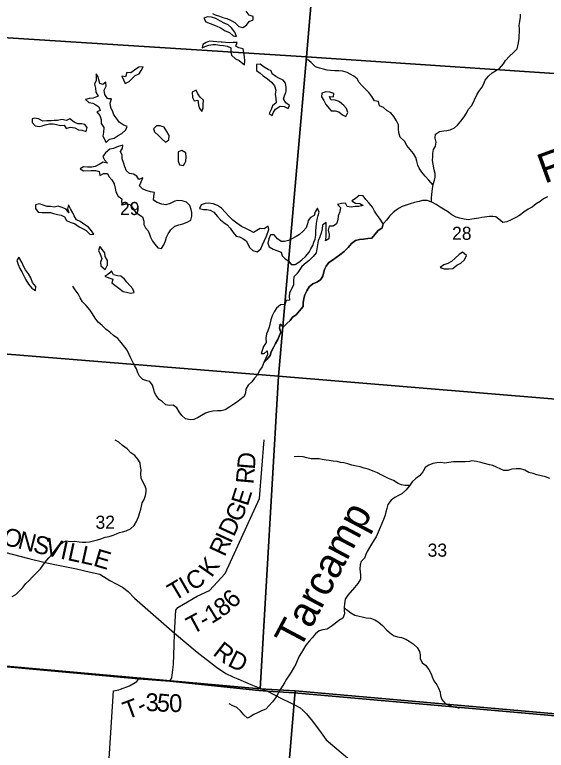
# Model space of a CAD drawing. Extents: x 1715311 to 2083412, y 146837 to 553079.
# Drawn here: x 1960786 to 1969763, y 377700 to 390110 of the extents above; entities that cross this region are included whole.
import ezdxf

# ---------------------------------------------------------------- set-up
doc = ezdxf.new("R2010")
doc.units = 0
for name, color, linetype in [('GM_X_County_Road', 7, 'Continuous'), ('GM_X_County_Road_Text', 7, 'Continuous'), ('GM_X_Minor_Lake', 7, 'Continuous'), ('GM_X_Minor_River', 7, 'Continuous'), ('GM_X_Minor_River_Text', 7, 'Continuous'), ('GM_X_Section', 7, 'Continuous'), ('GM_X_Section_Text', 7, 'Continuous'), ('GM_X_Township', 7, 'Continuous'), ('GM_X_Township_Road', 7, 'Continuous'), ('GM_X_Township_Road_Text', 7, 'Continuous'), ('GM_X_Township_ROW', 7, 'Continuous')]:
    doc.layers.add(name, color=color, linetype=linetype)

msp = doc.modelspace()

# ---------------------------------------------------------------- linework, layer by layer
at = {"layer": 'GM_X_County_Road'}
for points in [[(1960613, 381045), (1961027, 380934), (1961300, 380869), (1961548, 380819), (1961832, 380761), (1962066, 380704), (1962224, 380671), (1962390, 380567), (1962605, 380452), (1962702, 380380), (1962810, 380265), (1963484, 379677), (1963867, 379354), (1964196, 379103), (1964352, 378996), (1964470, 378940), (1964552, 378904)], [(1964552, 378904), (1964772, 378808), (1965054, 378699), (1965292, 378571), (1965431, 378505), (1965544, 378451), (1965604, 378417), (1965658, 378373), (1965716, 378315), (1965814, 378190), (1965960, 377994), (1966048, 377877), (1966550, 377450)]]:
    msp.add_lwpolyline(points, dxfattribs=at)
at = {"layer": 'GM_X_Minor_Lake'}
for points in [[(1964239, 389899), (1964271, 389881), (1964343, 389839), (1964411, 389811), (1964475, 389752), (1964529, 389744), (1964503, 389814), (1964449, 389887), (1964389, 389937), (1964325, 389967), (1964260, 390001), (1964184, 390046), (1964110, 390066), (1964044, 390074), (1963982, 390052)], [(1964127, 390130), (1964170, 390110), (1964246, 390084), (1964302, 390065), (1964366, 390047), (1964428, 390019), (1964501, 389979), (1964571, 389910), (1964641, 389892), (1964699, 389932), (1964747, 389998), (1964815, 390026), (1964811, 390080), (1964744, 390104), (1964696, 390172)], [(1963982, 390052), (1964012, 389990), (1964088, 389960), (1964158, 389934), (1964211, 389914), (1964239, 389899)], [(1964288, 389648), (1964274, 389649), (1964199, 389655), (1964137, 389660), (1964073, 389664), (1964017, 389644), (1963961, 389608), (1963950, 389554), (1964016, 389578), (1964066, 389598), (1964130, 389610), (1964182, 389607), (1964250, 389599), (1964312, 389593), (1964376, 389577), (1964438, 389550), (1964436, 389480), (1964446, 389430), (1964515, 389366), (1964579, 389340), (1964669, 389265)], [(1964669, 389265), (1964673, 389330), (1964667, 389402), (1964657, 389470), (1964642, 389534), (1964570, 389550), (1964518, 389580), (1964544, 389644), (1964476, 389644), (1964410, 389635), (1964344, 389641), (1964288, 389648)], [(1962945, 389211), (1962954, 389229), (1962880, 389226), (1962808, 389172), (1962750, 389128), (1962682, 389134), (1962658, 389064), (1962594, 389074)], [(1962594, 389074), (1962653, 388948), (1962721, 388982), (1962768, 389036), (1962820, 389082), (1962888, 389115), (1962924, 389167), (1962945, 389211)], [(1965363, 388799), (1965371, 388819), (1965371, 388885), (1965357, 388955), (1965319, 389007), (1965249, 389041), (1965198, 389070), (1965132, 389112), (1965116, 389162), (1965064, 389188), (1964998, 389224), (1964933, 389275), (1964867, 389271)], [(1964867, 389271), (1964870, 389167), (1964930, 389122), (1964982, 389080), (1965054, 389026), (1965123, 388972), (1965175, 388908), (1965195, 388839), (1965183, 388767), (1965196, 388695), (1965200, 388625), (1965138, 388571), (1965118, 388511), (1965084, 388446), (1965135, 388409), (1965158, 388465), (1965190, 388517), (1965268, 388565), (1965334, 388563), (1965404, 388528), (1965424, 388580), (1965366, 388623), (1965326, 388691), (1965340, 388743), (1965363, 388799)], [(1962370, 388693), (1962351, 388695), (1962309, 388763), (1962299, 388835), (1962332, 388905), (1962324, 388971), (1962274, 388931), (1962222, 388950), (1962206, 389012), (1962198, 389062), (1962164, 389114), (1962162, 389054), (1962162, 389002), (1962134, 388938), (1962148, 388870), (1962159, 388802), (1962193, 388735), (1962113, 388704), (1962043, 388698), (1961981, 388680), (1962037, 388630), (1962103, 388620), (1962155, 388589), (1962208, 388555), (1962232, 388493), (1962172, 388469), (1962226, 388409), (1962246, 388341), (1962245, 388273), (1962291, 388205), (1962287, 388129), (1962275, 388063), (1962328, 387952)], [(1963967, 388597), (1963977, 388669), (1963918, 388718), (1963880, 388774), (1963848, 388838), (1963784, 388802)], [(1962328, 387952), (1962388, 388008), (1962464, 388026), (1962536, 388070), (1962593, 388106), (1962665, 388167), (1962685, 388225), (1962615, 388250), (1962551, 388296), (1962515, 388346), (1962462, 388420), (1962442, 388472), (1962412, 388547), (1962397, 388617), (1962419, 388689), (1962370, 388693)], [(1963784, 388802), (1963788, 388714), (1963817, 388658), (1963877, 388668), (1963891, 388590), (1963903, 388540), (1963947, 388475), (1963969, 388539), (1963967, 388597)], [(1966248, 388649), (1966197, 388668), (1966127, 388674), (1966100, 388728), (1966168, 388724), (1966174, 388782), (1966106, 388802), (1966038, 388809), (1965972, 388785), (1965966, 388727), (1966008, 388663), (1966039, 388596), (1966129, 388486)], [(1966129, 388486), (1966197, 388486), (1966259, 388470), (1966324, 388423), (1966376, 388395), (1966412, 388459), (1966389, 388525), (1966343, 388577), (1966273, 388640), (1966248, 388649)], [(1962004, 388182), (1962009, 388206), (1961972, 388260), (1961914, 388268), (1961852, 388270), (1961788, 388297), (1961720, 388351), (1961660, 388325), (1961582, 388343), (1961508, 388323), (1961454, 388328), (1961400, 388320), (1961330, 388320), (1961262, 388316), (1961187, 388355), (1961121, 388367), (1961081, 388355)], [(1961081, 388355), (1961083, 388291), (1961134, 388235), (1961198, 388222), (1961250, 388236), (1961302, 388252), (1961376, 388268), (1961434, 388270), (1961494, 388255), (1961560, 388243), (1961624, 388245), (1961658, 388191), (1961724, 388215), (1961800, 388200), (1961863, 388168), (1961921, 388160), (1961993, 388140), (1962004, 388182)], [(1963368, 387982), (1963387, 387997), (1963396, 388075), (1963358, 388141), (1963310, 388213), (1963244, 388236), (1963179, 388236), (1963128, 388186)], [(1963128, 388186), (1963148, 388132), (1963212, 388074), (1963276, 388011), (1963335, 387957), (1963368, 387982)], [(1963079, 387121), (1963079, 387121), (1963009, 387142), (1962945, 387170), (1962895, 387224), (1962921, 387288), (1962950, 387356), (1962882, 387328), (1962848, 387384), (1962794, 387421), (1962726, 387429), (1962672, 387475), (1962647, 387545), (1962623, 387615), (1962603, 387679), (1962599, 387743), (1962572, 387800), (1962606, 387861), (1962614, 387911), (1962532, 387884), (1962456, 387854), (1962390, 387842), (1962318, 387780), (1962276, 387716), (1962303, 387662), (1962351, 387608), (1962279, 387622), (1962215, 387583), (1962145, 387547), (1962089, 387537), (1962017, 387537), (1961949, 387541), (1961893, 387512), (1961949, 387475), (1962077, 387479), (1962149, 387481), (1962215, 387463), (1962226, 387396), (1962286, 387430), (1962354, 387432), (1962374, 387382), (1962424, 387326), (1962466, 387256), (1962481, 387185), (1962495, 387121), (1962535, 387051), (1962593, 387005), (1962587, 386953), (1962606, 386903), (1962664, 386917), (1962728, 386906), (1962784, 386840), (1962828, 386776), (1962880, 386738), (1962943, 386700), (1962965, 386625), (1962967, 386573), (1962993, 386515), (1963040, 386461), (1963064, 386407), (1963082, 386357), (1963112, 386289)], [(1963545, 387798), (1963544, 387638), (1963570, 387576), (1963636, 387564), (1963663, 387616)], [(1963663, 387616), (1963674, 387638), (1963680, 387714), (1963678, 387782), (1963609, 387818), (1963545, 387798)], [(1963112, 386289), (1963152, 386237), (1963203, 386176), (1963265, 386168), (1963307, 386230), (1963332, 386294), (1963350, 386358), (1963376, 386414), (1963420, 386482), (1963490, 386544), (1963556, 386563), (1963628, 386581), (1963696, 386611), (1963758, 386643), (1963779, 386711), (1963777, 386775), (1963765, 386825), (1963743, 386891), (1963686, 386947), (1963614, 386968), (1963542, 386974), (1963488, 386966), (1963414, 386926), (1963340, 386904), (1963268, 386911), (1963194, 386941), (1963130, 386983), (1963136, 387047), (1963145, 387111), (1963079, 387121)], [(1967007, 386584), (1966944, 386678), (1966896, 386744), (1966864, 386796), (1966827, 386865), (1966771, 386929), (1966717, 386991), (1966671, 387053), (1966601, 387058), (1966537, 387004), (1966479, 386970), (1966543, 386928), (1966613, 386925), (1966669, 386891), (1966599, 386873), (1966535, 386876), (1966469, 386862), (1966401, 386874), (1966371, 386928), (1966305, 386926), (1966239, 386909), (1966289, 386856), (1966279, 386782), (1966249, 386717), (1966244, 386648), (1966222, 386583), (1966166, 386545), (1966094, 386545), (1966082, 386475), (1966096, 386401), (1966091, 386331), (1966035, 386295), (1966043, 386363), (1966046, 386431), (1966048, 386481), (1966048, 386543), (1966044, 386603), (1965986, 386561), (1965978, 386495), (1965962, 386427), (1965940, 386361), (1965909, 386293), (1965897, 386227), (1965889, 386161), (1965875, 386095), (1965827, 386028), (1965758, 385966), (1965706, 385922), (1965636, 385862), (1965590, 385796), (1965548, 385740), (1965498, 385686), (1965493, 385622), (1965493, 385546), (1965461, 385484), (1965429, 385414), (1965421, 385362), (1965424, 385292), (1965372, 385287), (1965348, 385219), (1965274, 385215), (1965208, 385159), (1965168, 385099), (1965132, 385031), (1965113, 384961), (1965097, 384891), (1965085, 384841), (1965059, 384779), (1965039, 384725), (1965026, 384655), (1965034, 384579), (1964988, 384511), (1964968, 384459), (1964946, 384393), (1965000, 384393), (1965050, 384439), (1965053, 384377), (1964995, 384243)], [(1961605, 386709), (1961625, 386700), (1961662, 386636), (1961732, 386604), (1961798, 386585), (1961872, 386533), (1961942, 386499), (1961993, 386467), (1962063, 386400), (1962125, 386406), (1962081, 386466), (1962030, 386525), (1961968, 386565), (1961894, 386621), (1961832, 386651), (1961790, 386715), (1961767, 386766), (1961729, 386836), (1961697, 386900), (1961679, 386836), (1961701, 386770), (1961655, 386832), (1961587, 386860), (1961523, 386878), (1961455, 386861), (1961389, 386877), (1961335, 386875), (1961266, 386899), (1961204, 386920), (1961136, 386904)], [(1961136, 386904), (1961137, 386840), (1961181, 386780), (1961249, 386773), (1961319, 386773), (1961389, 386771), (1961443, 386757), (1961507, 386740), (1961571, 386726), (1961605, 386709)], [(1964397, 386717), (1964344, 386775), (1964277, 386847), (1964211, 386891), (1964135, 386918), (1964055, 386930), (1964003, 386924), (1963933, 386904), (1963909, 386838), (1963975, 386824), (1964029, 386824), (1964085, 386814), (1964151, 386776), (1964212, 386707), (1964262, 386647), (1964320, 386605), (1964372, 386563), (1964427, 386506), (1964477, 386438), (1964527, 386376), (1964585, 386362), (1964639, 386334), (1964694, 386293), (1964730, 386233), (1964750, 386183), (1964810, 386133), (1964880, 386109), (1964942, 386159), (1964968, 386229), (1965000, 386290)], [(1965901, 386848), (1965861, 386786), (1965843, 386722), (1965781, 386688), (1965741, 386636), (1965729, 386582), (1965708, 386516), (1965656, 386456), (1965596, 386401), (1965540, 386369), (1965468, 386327), (1965410, 386301), (1965344, 386283), (1965288, 386283), (1965224, 386328), (1965168, 386398), (1965108, 386396), (1965078, 386328), (1965062, 386258), (1965082, 386192), (1965152, 386154), (1965213, 386134), (1965285, 386105), (1965301, 386041), (1965351, 385989), (1965409, 385959), (1965454, 385893), (1965524, 385898), (1965586, 385934), (1965636, 385976), (1965699, 386032), (1965759, 386104), (1965789, 386158), (1965821, 386214), (1965839, 386270), (1965858, 386322), (1965870, 386392), (1965871, 386409)], [(1965871, 386409), (1965874, 386462), (1965878, 386528), (1965882, 386586), (1965895, 386654), (1965911, 386724), (1965925, 386778), (1965901, 386848)], [(1965000, 386290), (1965032, 386364), (1965063, 386434), (1965077, 386486), (1965067, 386542), (1964997, 386499), (1964931, 386505), (1964873, 386467), (1964821, 386437), (1964757, 386471), (1964679, 386508), (1964615, 386538), (1964540, 386594), (1964472, 386644), (1964408, 386705), (1964397, 386717)], [(1964995, 384243), (1965047, 384299), (1965101, 384359), (1965116, 384425), (1965158, 384495), (1965190, 384565), (1965228, 384633), (1965250, 384685), (1965283, 384754), (1965257, 384823), (1965271, 384889), (1965323, 384846), (1965381, 384898), (1965437, 384950), (1965475, 385008), (1965537, 385046), (1965598, 385116), (1965656, 385188), (1965658, 385250), (1965668, 385320), (1965684, 385386), (1965717, 385450), (1965759, 385517), (1965819, 385569), (1965887, 385599), (1965949, 385635), (1965989, 385699), (1965999, 385751), (1966020, 385811), (1966044, 385869), (1966090, 385927), (1966154, 385970), (1966216, 386012), (1966278, 386058), (1966350, 386116), (1966415, 386180), (1966471, 386249), (1966541, 386303), (1966611, 386315), (1966679, 386323), (1966747, 386337), (1966817, 386340), (1966869, 386400), (1966917, 386462), (1966989, 386516), (1967007, 386584)], [(1962238, 386181), (1962222, 386200), (1962200, 386134), (1962230, 386068), (1962256, 385999), (1962235, 385933), (1962241, 385871), (1962313, 385809)], [(1962313, 385809), (1962353, 385891), (1962353, 385961), (1962312, 386031), (1962306, 386095), (1962264, 386150), (1962238, 386181)], [(1968414, 386045), (1968349, 386105), (1968292, 386063), (1968222, 386001), (1968160, 385944), (1968102, 385912), (1968032, 385890), (1967970, 385844), (1968036, 385822), (1968118, 385825)], [(1960855, 386020), (1960821, 385966), (1960846, 385896), (1960874, 385830), (1960904, 385770), (1960940, 385704), (1960975, 385639), (1961017, 385565), (1961073, 385497), (1961112, 385472)], [(1961112, 385472), (1961135, 385457), (1961141, 385527), (1961089, 385591), (1961059, 385669), (1961020, 385741), (1960968, 385806), (1960942, 385856), (1960912, 385924), (1960855, 386020)], [(1968118, 385825), (1968184, 385831), (1968252, 385883), (1968320, 385917), (1968380, 385975), (1968414, 386045)], [(1962306, 385697), (1962378, 385671), (1962442, 385647), (1962426, 385589), (1962478, 385546), (1962544, 385498), (1962615, 385442), (1962673, 385430), (1962743, 385413), (1962801, 385421), (1962779, 385483), (1962734, 385536), (1962682, 385600), (1962638, 385650), (1962576, 385700), (1962520, 385706), (1962456, 385723), (1962419, 385791)], [(1962419, 385791), (1962392, 385757), (1962359, 385726), (1962306, 385697)]]:
    msp.add_lwpolyline(points, dxfattribs=at)
at = {"layer": 'GM_X_Minor_River'}
for points in [[(1968504, 388580), (1968591, 388758), (1968623, 388812), (1968675, 388880), (1968703, 388932), (1968731, 389004), (1968786, 389075), (1968850, 389127), (1968920, 389175), (1968970, 389201), (1969042, 389281), (1969074, 389337), (1969140, 389408), (1969207, 389474), (1969269, 389534), (1969283, 389586), (1969293, 389636), (1969303, 389708), (1969307, 389760), (1969310, 389816), (1969310, 389874), (1969306, 389926), (1969316, 389996), (1969326, 390068), (1969327, 390122)], [(1967852, 387237), (1967777, 387316), (1967720, 387388), (1967664, 387454), (1967618, 387522), (1967596, 387573), (1967577, 387637), (1967559, 387701), (1967521, 387767), (1967463, 387837), (1967408, 387901), (1967366, 387976), (1967298, 388046), (1967275, 388116), (1967267, 388186), (1967267, 388250), (1967235, 388318), (1967190, 388390), (1967138, 388457), (1967076, 388489), (1967014, 388543), (1966944, 388575), (1966927, 388647), (1966863, 388658), (1966815, 388730), (1966769, 388800), (1966710, 388856), (1966652, 388909), (1966602, 388967), (1966572, 389029), (1966512, 389073), (1966451, 389109), (1966399, 389134), (1966325, 389158), (1966257, 389166), (1966191, 389166), (1966117, 389169), (1966065, 389177), (1966001, 389193), (1965933, 389207), (1965864, 389233), (1965792, 389302), (1965728, 389354)], [(1967826, 386949), (1967824, 387021), (1967828, 387075), (1967835, 387125), (1967843, 387175), (1967853, 387243), (1967877, 387319), (1967887, 387369), (1967884, 387433), (1967872, 387492), (1967854, 387586), (1967844, 387650), (1967845, 387718), (1967847, 387770), (1967859, 387838), (1967893, 387892), (1967901, 387958), (1967886, 388026), (1967894, 388096), (1967962, 388140), (1968032, 388151), (1968084, 388159), (1968142, 388169), (1968212, 388203), (1968266, 388249), (1968318, 388315), (1968378, 388386), (1968415, 388450), (1968445, 388512), (1968504, 388580)], [(1968504, 386661), (1968444, 386651), (1968374, 386663), (1968305, 386678), (1968239, 386696), (1968169, 386736), (1968095, 386792), (1968029, 386829), (1967970, 386863), (1967902, 386907), (1967830, 386947), (1967752, 386976), (1967674, 386978), (1967616, 386960), (1967536, 386942), (1967464, 386917), (1967396, 386897), (1967328, 386873), (1967278, 386847), (1967228, 386813), (1967178, 386773), (1967114, 386710), (1967068, 386650), (1967007, 386584), (1966989, 386516), (1966917, 386462), (1966869, 386400), (1966817, 386340), (1966747, 386337), (1966679, 386323), (1966611, 386315), (1966541, 386303), (1966471, 386249), (1966415, 386180), (1966350, 386116), (1966278, 386058), (1966216, 386012), (1966154, 385970), (1966090, 385927), (1966044, 385869), (1966020, 385811), (1965999, 385751), (1965989, 385699), (1965949, 385635), (1965887, 385599), (1965819, 385569), (1965759, 385517), (1965717, 385450), (1965684, 385386), (1965668, 385320), (1965658, 385250), (1965656, 385188), (1965598, 385116), (1965537, 385046), (1965475, 385008), (1965437, 384950), (1965381, 384898), (1965323, 384846), (1965271, 384889), (1965257, 384823), (1965283, 384754), (1965250, 384685), (1965228, 384633), (1965190, 384565), (1965158, 384495), (1965116, 384425), (1965101, 384359), (1965047, 384299), (1964995, 384243), (1964963, 384169), (1964921, 384105), (1964884, 384033), (1964838, 383979), (1964788, 383918), (1964726, 383862), (1964690, 383794), (1964686, 383728), (1964659, 383670), (1964589, 383610), (1964533, 383568), (1964467, 383530), (1964417, 383496), (1964339, 383445), (1964271, 383425), (1964209, 383425), (1964133, 383419), (1964059, 383402), (1964007, 383388), (1963941, 383348), (1963883, 383314), (1963813, 383280), (1963749, 383274), (1963673, 383291), (1963611, 383347), (1963561, 383411), (1963526, 383479), (1963460, 383520), (1963394, 383516), (1963340, 383526), (1963276, 383582), (1963224, 383617)], [(1969782, 387036), (1969716, 387002), (1969662, 386958), (1969592, 386920), (1969522, 386863), (1969456, 386827), (1969384, 386779), (1969312, 386725), (1969240, 386681), (1969168, 386648), (1969099, 386614), (1969029, 386602), (1968964, 386660), (1968910, 386700), (1968858, 386706), (1968804, 386707), (1968676, 386691), (1968622, 386675), (1968504, 386661)], [(1963224, 383617), (1963173, 383685), (1963149, 383735), (1963133, 383789), (1963111, 383859), (1963070, 383923), (1963018, 383933), (1962950, 383958), (1962892, 384014), (1962868, 384066), (1962845, 384134), (1962809, 384192), (1962775, 384260), (1962739, 384327), (1962720, 384379), (1962684, 384449), (1962648, 384503), (1962582, 384579), (1962529, 384646), (1962455, 384696), (1962391, 384756), (1962331, 384800), (1962266, 384867), (1962198, 384923), (1962146, 384991), (1962102, 385063), (1962055, 385130), (1961995, 385202), (1961929, 385266), (1961892, 385334), (1961856, 385402), (1961806, 385469), (1961768, 385533)], [(1962748, 382719), (1962684, 382786), (1962608, 382842), (1962547, 382896), (1962481, 382930)], [(1960745, 380292), (1960803, 380328), (1960865, 380391), (1960921, 380447), (1960972, 380511), (1961028, 380563), (1961086, 380625), (1961150, 380687), (1961222, 380763), (1961262, 380815), (1961303, 380874), (1961363, 380944), (1961421, 381010), (1961475, 381082), (1961527, 381148), (1961592, 381208), (1961658, 381236), (1961729, 381223), (1961803, 381227), (1961877, 381219), (1961931, 381209), (1961985, 381211), (1962051, 381216), (1962115, 381232), (1962187, 381252), (1962243, 381266), (1962315, 381294), (1962383, 381309), (1962447, 381327), (1962503, 381353), (1962555, 381373), (1962609, 381383), (1962671, 381404), (1962741, 381438), (1962803, 381494), (1962842, 381562), (1962876, 381640), (1962900, 381714), (1962916, 381766), (1962926, 381820), (1962941, 381874), (1962973, 381932), (1962993, 381996), (1963007, 382060), (1963007, 382112), (1962982, 382166), (1962944, 382240), (1962922, 382292), (1962916, 382368), (1962919, 382433), (1962913, 382485), (1962903, 382547), (1962865, 382613), (1962816, 382671), (1962748, 382719)], [(1967457, 382167), (1967380, 382167), (1967316, 382178), (1967264, 382200), (1967182, 382250), (1967100, 382288), (1967041, 382311), (1966985, 382343), (1966913, 382383), (1966857, 382405), (1966753, 382442), (1966689, 382460), (1966620, 382482), (1966558, 382496), (1966480, 382511), (1966410, 382533), (1966344, 382547), (1966288, 382557), (1966234, 382570), (1966164, 382580), (1966096, 382590), (1966044, 382594), (1965980, 382604), (1965927, 382617), (1965863, 382619), (1965793, 382619), (1965721, 382635), (1965655, 382650), (1965577, 382658), (1965507, 382652)], [(1968504, 382584), (1968466, 382572), (1968394, 382564), (1968324, 382569), (1968246, 382565), (1968194, 382565), (1968118, 382557), (1968048, 382544), (1967979, 382556), (1967917, 382550), (1967845, 382536), (1967779, 382512), (1967717, 382469), (1967676, 382397), (1967624, 382331), (1967558, 382287), (1967500, 382227), (1967452, 382159), (1967389, 382089), (1967321, 382027), (1967269, 382000), (1967205, 381966), (1967143, 381918), (1967089, 381848), (1967071, 381778), (1967055, 381722), (1967040, 381666), (1967012, 381596), (1966986, 381528), (1966958, 381456), (1966925, 381378), (1966889, 381300), (1966859, 381248), (1966809, 381176), (1966779, 381120), (1966740, 381052), (1966716, 381001), (1966694, 380941), (1966634, 380883), (1966620, 380829), (1966614, 380761), (1966625, 380660), (1966625, 380588), (1966579, 380514), (1966525, 380447), (1966412, 380315), (1966366, 380247), (1966354, 380171), (1966348, 380115), (1966347, 380065), (1966355, 380001), (1966327, 379929), (1966261, 379887), (1966195, 379837), (1966131, 379787), (1966063, 379741), (1965991, 379734), (1965929, 379716), (1965864, 379666), (1965810, 379598), (1965762, 379544), (1965700, 379474), (1965662, 379404), (1965632, 379352), (1965589, 379285), (1965557, 379211), (1965533, 379155), (1965495, 379085), (1965455, 379017), (1965410, 378951), (1965376, 378899), (1965350, 378847), (1965316, 378793), (1965268, 378725), (1965228, 378653), (1965191, 378585), (1965141, 378517), (1965075, 378449), (1965027, 378391), (1964953, 378366), (1964899, 378338), (1964823, 378302), (1964765, 378262), (1964715, 378244), (1964657, 378299), (1964597, 378363), (1964535, 378419), (1964467, 378449), (1964406, 378482)], [(1969823, 382284), (1969751, 382314), (1969679, 382330), (1969605, 382349), (1969540, 382369), (1969470, 382389), (1969398, 382425), (1969330, 382447), (1969256, 382448), (1969182, 382442), (1969114, 382422), (1969046, 382422), (1968994, 382440), (1968922, 382475), (1968858, 382503), (1968802, 382517), (1968721, 382537), (1968657, 382554), (1968587, 382570), (1968504, 382584)], [(1966348, 380105), (1966409, 380057), (1966463, 380018), (1966529, 379982), (1966603, 379962), (1966655, 379952), (1966721, 379937), (1966795, 379927), (1966870, 379899), (1966924, 379865), (1966996, 379806), (1967072, 379726), (1967141, 379666), (1967193, 379632), (1967253, 379615), (1967317, 379605), (1967391, 379573), (1967447, 379539), (1967516, 379496), (1967584, 379436), (1967624, 379366), (1967634, 379308), (1967631, 379248), (1967667, 379175), (1967723, 379135), (1967781, 379065), (1967814, 379001), (1967836, 378937), (1967866, 378872), (1967914, 378802), (1967940, 378750), (1967971, 378680), (1967979, 378626), (1968001, 378558), (1968057, 378491), (1968126, 378459), (1968184, 378433), (1968256, 378419), (1968291, 378411)]]:
    msp.add_lwpolyline(points, dxfattribs=at)
at = {"layer": 'GM_X_Section'}
for points in [[(1966160, 394612), (1965715, 389402), (1960228, 389748), (1960694, 395084)], [(1966160, 394612), (1971846, 394151), (1971405, 389017), (1965715, 389402)], [(1960228, 389748), (1965715, 389402), (1965243, 384014), (1959756, 384455)], [(1965715, 389402), (1971405, 389017), (1971010, 383534), (1965243, 384014)], [(1959756, 384455), (1965243, 384014), (1964933, 378739), (1960259, 379152), (1959343, 379221)], [(1965243, 384014), (1971010, 383534), (1970553, 378257), (1965523, 378701), (1964933, 378739)], [(1960259, 379152), (1964933, 378739), (1965523, 378701), (1965082, 373496), (1959801, 373922)], [(1965523, 378701), (1970553, 378257), (1970801, 378233), (1970470, 373048), (1965082, 373496)]]:
    msp.add_lwpolyline(points, close=True, dxfattribs=at)
at = {"layer": 'GM_X_Township'}
for points in [[(1970494, 378230), (1965504, 378667), (1965054, 378699), (1964907, 378710), (1963404, 378864), (1962883, 378907), (1957576, 379388), (1953709, 379667), (1953922, 382139), (1954131, 384197), (1954148, 384242), (1954163, 384351), (1954169, 384420), (1954179, 384547), (1954712, 390316)], [(1953358, 375895), (1953709, 379667), (1957576, 379388), (1962883, 378907), (1963404, 378864), (1964907, 378710), (1965054, 378699), (1965504, 378667), (1970494, 378230), (1975651, 377844), (1976132, 377779), (1982964, 377254)]]:
    msp.add_lwpolyline(points, dxfattribs=at)
at = {"layer": 'GM_X_Township_Road'}
for points in [[(1963484, 379677), (1963509, 380062), (1963540, 380107), (1963638, 380167), (1963865, 380300), (1964076, 380396), (1964340, 380682), (1964919, 381947), (1964999, 382939)], [(1962570, 378731), (1962723, 378787), (1962848, 378859), (1962883, 378907), (1963404, 378864), (1963438, 378921), (1963466, 379145), (1963479, 379471), (1963484, 379677)]]:
    msp.add_lwpolyline(points, dxfattribs=at)
at = {"layer": 'GM_X_Township_ROW'}
msp.add_lwpolyline([(1960313, 374549), (1960881, 374505), (1960924, 374512), (1961445, 374806), (1961734, 375263), (1961941, 375456), (1962043, 375551), (1962256, 375623), (1962453, 378701), (1962545, 378722), (1962570, 378731)], dxfattribs=at)

# ---------------------------------------------------------------- texts
at = {"layer": 'GM_X_County_Road_Text'}
for s, rotation, p in [('O', 346.5778, (1960567, 381173)), ('N', 345.7111, (1960823, 381112)), ('S', 346.0924, (1961081, 381047)), ('V', 347.1971, (1961283, 380997)), ('I', 347.8256, (1961544, 380937)), ('L', 347.8668, (1961665, 380911)), ('L', 347.6218, (1961884, 380864)), ('E', 343.483, (1962098, 380818)), ('R', 322.0388, (1964117, 379319)), ('D', 333.5419, (1964366, 379133))]:
    msp.add_text(s, height=300, rotation=rotation, dxfattribs=at).set_placement(p)
at = {"layer": 'GM_X_Minor_River_Text'}
for s, rotation, p in [('Flint', 19.9912, (1969731, 387256)), ('Tarcamp', 62.0216, (1965595, 379377))]:
    msp.add_text(s, height=500, rotation=rotation, dxfattribs=at).set_placement(p)
at = {"layer": 'GM_X_Section_Text'}
for s, p in [('29', (1962565, 386730)), ('28', (1968172, 386312)), ('32', (1962151, 381437)), ('33', (1967759, 380966))]:
    msp.add_text(s, height=221, rotation=0, dxfattribs=at).set_placement(p)
at = {"layer": 'GM_X_Township_Road_Text'}
for s, rotation, p in [('D', 85.3078, (1964840, 382430)), ('R', 84.8438, (1964817, 382182)), ('E', 72.2012, (1964720, 381806)), ('G', 65.5532, (1964597, 381530)), ('D', 65.2985, (1964486, 381289)), ('I', 65.2955, (1964435, 381177)), ('R', 65.1957, (1964331, 380953)), ('K', 54.8554, (1964111, 380602)), ('C', 27.9616, (1963779, 380386)), ('T', 30.7602, (1963482, 380211)), ('I', 29.9395, (1963674, 380326)), ('6', 43.8173, (1964470, 380075)), ('8', 36.5978, (1964290, 379939)), ('1', 31.6549, (1964110, 379826)), ('T', 28.4839, (1963789, 379649)), ('-', 29.236, (1963990, 379759)), ('3', 1.6078, (1963001, 378357)), ('5', 354.2431, (1963174, 378363)), ('0', 1.3161, (1963397, 378343)), ('T', 20.4434, (1962682, 378217)), ('-', 26.9831, (1962926, 378310))]:
    msp.add_text(s, height=300, rotation=rotation, dxfattribs=at).set_placement(p)

doc.saveas('drawing.dxf')
